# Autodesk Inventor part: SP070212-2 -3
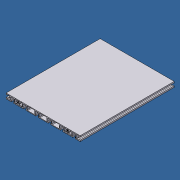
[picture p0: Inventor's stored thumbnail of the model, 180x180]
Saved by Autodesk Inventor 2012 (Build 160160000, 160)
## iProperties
Created: 2012-06
Part Number: SP070212-2 -3
Material: Aluminum-6061
Description: TAP ALL4 M8
Document SubType Name: Modeling
Designer: Administrator
Stock Number: 20.1077 PROFILE 19X270
Density: 2.71 g/cm^3
FINISH: CLEAR ANODIZED
Author: Administrator
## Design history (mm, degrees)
sketch "Sketch1"
  geometry: L1 (103.3, 5)-(103.3, -5) reference; L2 (101.3, -7)-(100.091, -7) reference; L3 (98.677, -6.414)-(93.769, -1.506) reference; L4 (91.506, -3.769)-(93.03, -5.293) reference; L5 (92.323, -7)-(87.677, -7) reference; L6 (86.97, -5.293)-(88.494, -3.769) reference; L7 (86.231, -1.506)-(81.323, -6.414) reference; L8 (79.909, -7)-(78.7, -7) reference; L9 (76.7, -5)-(76.7, 5) reference; L10 (78.7, 7)-(79.909, 7) reference; L11 (81.323, 6.414)-(86.231, 1.506) reference; L12 (88.494, 3.769)-(86.97, 5.293) reference; L13 (87.677, 7)-(92.323, 7) reference; L14 (93.03, 5.293)-(91.506, 3.769) reference; L15 (93.769, 1.506)-(98.677, 6.414) reference; L16 (100.091, 7)-(101.3, 7) reference; L17 (-76.7, 5)-(-76.7, -5) reference; L18 (-78.7, -7)-(-79.909, -7) reference; L19 (-81.323, -6.414)-(-86.231, -1.506) reference; L20 (-88.494, -3.769)-(-86.97, -5.293) reference; L21 (-87.677, -7)-(-92.323, -7) reference; L22 (-93.03, -5.293)-(-91.506, -3.769) reference; L23 (-93.769, -1.506)-(-98.677, -6.414) reference; L24 (-100.091, -7)-(-101.3, -7) reference; L25 (-103.3, -5)-(-103.3, 5) reference; L26 (-101.3, 7)-(-100.091, 7) reference; L27 (-98.677, 6.414)-(-93.769, 1.506) reference; L28 (-91.506, 3.769)-(-93.03, 5.293) reference; L29 (-92.323, 7)-(-87.677, 7) reference; L30 (-86.97, 5.293)-(-88.494, 3.769) reference; L31 (-86.231, 1.506)-(-81.323, 6.414) reference; L32 (-79.909, 7)-(-78.7, 7) reference; L33 (33.7, 7)-(56.3, 7) reference; L34 (58.3, 5)-(58.3, -5) reference; L35 (56.3, -7)-(33.7, -7) reference; L36 (31.7, -5)-(31.7, 5) reference; L37 (-11.3, 7)-(11.3, 7) reference; L38 (13.3, 5)-(13.3, -5) reference; L39 (11.3, -7)-(-11.3, -7) reference; L40 (-13.3, -5)-(-13.3, 5) reference; L41 (-56.3, 7)-(-33.7, 7) reference; L42 (-31.7, 5)-(-31.7, -5) reference; L43 (-33.7, -7)-(-56.3, -7) reference; L44 (-58.3, -5)-(-58.3, 5) reference; L45 (135, -4.25)-(130.5, -4.25) reference; L46 (130.5, -4.25)-(130.5, -7) reference; L47 (130.5, -7)-(122.8, -7) reference; L48 (121.8, -6)-(121.8, 6) reference; L49 (122.8, 7)-(130.5, 7) reference; L50 (130.5, 4.25)-(135, 4.25) reference; L51 (135, 4.25)-(135, 9.5) reference; L52 (-135, 9.5)-(135, 9.5) reference; L53 (-135, 4.25)-(-130.5, 4.25) reference; L54 (-130.5, 7)-(-122.8, 7) reference; L55 (-121.8, 6)-(-121.8, -6) reference; L56 (-122.8, -7)-(-130.5, -7) reference; L57 (-130.5, -7)-(-130.5, -4.25) reference; L58 (-130.5, -4.25)-(-135, -4.25) reference; L59 (-135, -9.5)-(-135, -4.25) reference; L60 (-116.6, -9.5)-(-116.6, -5) reference; L61 (-119.3, -5)-(-119.3, 3.5) reference; L62 (-119.3, 3.5)-(-117, 5.8) reference; L63 (-117, 5.8)-(-108, 5.8) reference; L64 (-108, 5.8)-(-105.7, 3.5) reference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; A1 r 2 centre (101.3, 5) between (103.3, 5) and (101.3, 7) reference; A2 r 2 centre (101.3, -5) between (101.3, -7) and (103.3, -5) reference; A3 r 2 centre (100.091, -5) between (98.677, -6.414) and (100.091, -7) reference; A4 r 0.3 centre (93.557, -1.718) between (93.769, -1.506) and (93.287, -1.588) reference; A5 r 3.65 centre (90, 0) between (91.588, -3.287) and (93.287, -1.588) reference; A6 r 0.3 centre (91.718, -3.557) between (91.588, -3.287) and (91.506, -3.769) reference; A7 r 1 centre (92.323, -6) between (92.323, -7) and (93.03, -5.293) reference; A8 r 1 centre (87.677, -6) between (86.97, -5.293) and (87.677, -7) reference; A9 r 0.3 centre (88.282, -3.557) between (88.494, -3.769) and (88.412, -3.287) reference; A10 r 3.65 centre (90, 0) between (86.713, -1.588) and (88.412, -3.287) reference; A11 r 0.3 centre (86.443, -1.718) between (86.713, -1.588) and (86.231, -1.506) reference; A12 r 2 centre (79.909, -5) between (79.909, -7) and (81.323, -6.414) reference; A13 r 2 centre (78.7, -5) between (76.7, -5) and (78.7, -7) reference; A14 r 2 centre (78.7, 5) between (78.7, 7) and (76.7, 5) reference; A15 r 2 centre (79.909, 5) between (81.323, 6.414) and (79.909, 7) reference; A16 r 0.3 centre (86.443, 1.718) between (86.231, 1.506) and (86.713, 1.588) reference; A17 r 3.65 centre (90, 0) between (88.412, 3.287) and (86.713, 1.588) reference; A18 r 0.3 centre (88.282, 3.557) between (88.412, 3.287) and (88.494, 3.769) reference; A19 r 1 centre (87.677, 6) between (87.677, 7) and (86.97, 5.293) reference; A20 r 1 centre (92.323, 6) between (93.03, 5.293) and (92.323, 7) reference; A21 r 0.3 centre (91.718, 3.557) between (91.506, 3.769) and (91.588, 3.287) reference; A22 r 3.65 centre (90, 0) between (93.287, 1.588) and (91.588, 3.287) reference; A23 r 0.3 centre (93.557, 1.718) between (93.287, 1.588) and (93.769, 1.506) reference; A24 r 2 centre (100.091, 5) between (100.091, 7) and (98.677, 6.414) reference; A25 r 2 centre (-78.7, 5) between (-76.7, 5) and (-78.7, 7) reference; A26 r 2 centre (-78.7, -5) between (-78.7, -7) and (-76.7, -5) reference; A27 r 2 centre (-79.909, -5) between (-81.323, -6.414) and (-79.909, -7) reference; A28 r 0.3 centre (-86.443, -1.718) between (-86.231, -1.506) and (-86.713, -1.588) reference; A29 r 3.65 centre (-90, 0) between (-88.412, -3.287) and (-86.713, -1.588) reference; A30 r 0.3 centre (-88.282, -3.557) between (-88.412, -3.287) and (-88.494, -3.769) reference; A31 r 1 centre (-87.677, -6) between (-87.677, -7) and (-86.97, -5.293) reference; A32 r 1 centre (-92.323, -6) between (-93.03, -5.293) and (-92.323, -7) reference; A33 r 0.3 centre (-91.718, -3.557) between (-91.506, -3.769) and (-91.588, -3.287) reference; A34 r 3.65 centre (-90, 0) between (-93.287, -1.588) and (-91.588, -3.287) reference; A35 r 0.3 centre (-93.557, -1.718) between (-93.287, -1.588) and (-93.769, -1.506) reference; A36 r 2 centre (-100.091, -5) between (-100.091, -7) and (-98.677, -6.414) reference; A37 r 2 centre (-101.3, -5) between (-103.3, -5) and (-101.3, -7) reference; A38 r 2 centre (-101.3, 5) between (-101.3, 7) and (-103.3, 5) reference; A39 r 2 centre (-100.091, 5) between (-98.677, 6.414) and (-100.091, 7) reference; A40 r 0.3 centre (-93.557, 1.718) between (-93.769, 1.506) and (-93.287, 1.588) reference; A41 r 3.65 centre (-90, 0) between (-91.588, 3.287) and (-93.287, 1.588) reference; A42 r 0.3 centre (-91.718, 3.557) between (-91.588, 3.287) and (-91.506, 3.769) reference; A43 r 1 centre (-92.323, 6) between (-92.323, 7) and (-93.03, 5.293) reference; A44 r 1 centre (-87.677, 6) between (-86.97, 5.293) and (-87.677, 7) reference; A45 r 0.3 centre (-88.282, 3.557) between (-88.494, 3.769) and (-88.412, 3.287) reference; A46 r 3.65 centre (-90, 0) between (-86.713, 1.588) and (-88.412, 3.287) reference; A47 r 0.3 centre (-86.443, 1.718) between (-86.713, 1.588) and (-86.231, 1.506) reference; A48 r 2 centre (-79.909, 5) between (-79.909, 7) and (-81.323, 6.414) reference; A49 r 2 centre (56.3, 5) between (58.3, 5) and (56.3, 7) reference; A50 r 2 centre (56.3, -5) between (56.3, -7) and (58.3, -5) reference; A51 r 2 centre (33.7, -5) between (31.7, -5) and (33.7, -7) reference; A52 r 2 centre (33.7, 5) between (33.7, 7) and (31.7, 5) reference; A53 r 2 centre (11.3, 5) between (13.3, 5) and (11.3, 7) reference; A54 r 2 centre (11.3, -5) between (11.3, -7) and (13.3, -5) reference; A55 r 2 centre (-11.3, -5) between (-13.3, -5) and (-11.3, -7) reference; A56 r 2 centre (-11.3, 5) between (-11.3, 7) and (-13.3, 5) reference; A57 r 2 centre (-33.7, 5) between (-31.7, 5) and (-33.7, 7) reference; A58 r 2 centre (-33.7, -5) between (-33.7, -7) and (-31.7, -5) reference; A59 r 2 centre (-56.3, -5) between (-58.3, -5) and (-56.3, -7) reference; A60 r 2 centre (-56.3, 5) between (-56.3, 7) and (-58.3, 5) reference; A61 r 1 centre (122.8, -6) between (121.8, -6) and (122.8, -7) reference; A62 r 1 centre (122.8, 6) between (122.8, 7) and (121.8, 6) reference; A63 r 1 centre (-122.8, 6) between (-121.8, 6) and (-122.8, 7) reference; A64 r 1 centre (-122.8, -6) between (-122.8, -7) and (-121.8, -6) reference
  constraints: 248 end point, 128 point on circle, 64 centre point, 44 horizontal, 36 vertical, 360 other
extrude "Extrusion1" new body sketch "Sketch1" stored distance "d0" = 343; taper "d1" = 0 deg
thread "Thread1" dims "d2" = 25.4, "d3" = 0
thread "Thread2" dims "d4" = 25.4, "d5" = 0
thread "Thread3" dims "d6" = 25.4, "d7" = 0
thread "Thread4" dims "d8" = 25.4, "d9" = 0
thread "Thread5" dims "d10" = 25.4, "d11" = 0
thread "Thread6" dims "d12" = 25.4, "d13" = 0
thread "Thread7" dims "d14" = 25.4, "d15" = 0
thread "Thread8" dims "d16" = 25.4, "d17" = 0
thread "Thread9" dims "d18" = 25.4, "d19" = 0
thread "Thread10" dims "d20" = 25.4, "d21" = 0
thread "Thread11" dims "d22" = 25.4, "d23" = 0
thread "Thread12" dims "d24" = 25.4, "d25" = 0
thread "Thread13" dims "d26" = 25.4, "d27" = 0
thread "Thread14" dims "d28" = 25.4, "d29" = 0
thread "Thread15" dims "d30" = 25.4, "d31" = 0
thread "Thread16" dims "d32" = 25.4, "d33" = 0
body "Solid1"
